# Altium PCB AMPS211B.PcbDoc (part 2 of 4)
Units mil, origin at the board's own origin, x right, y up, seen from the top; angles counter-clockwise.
Board outline 3600 x 2600 mil, 4 copper layers (Top Layer, GND, Power, Bottom Layer), stack 61.6 mil thick; 202 components, 101 nets, 561 pads, 317 vias.
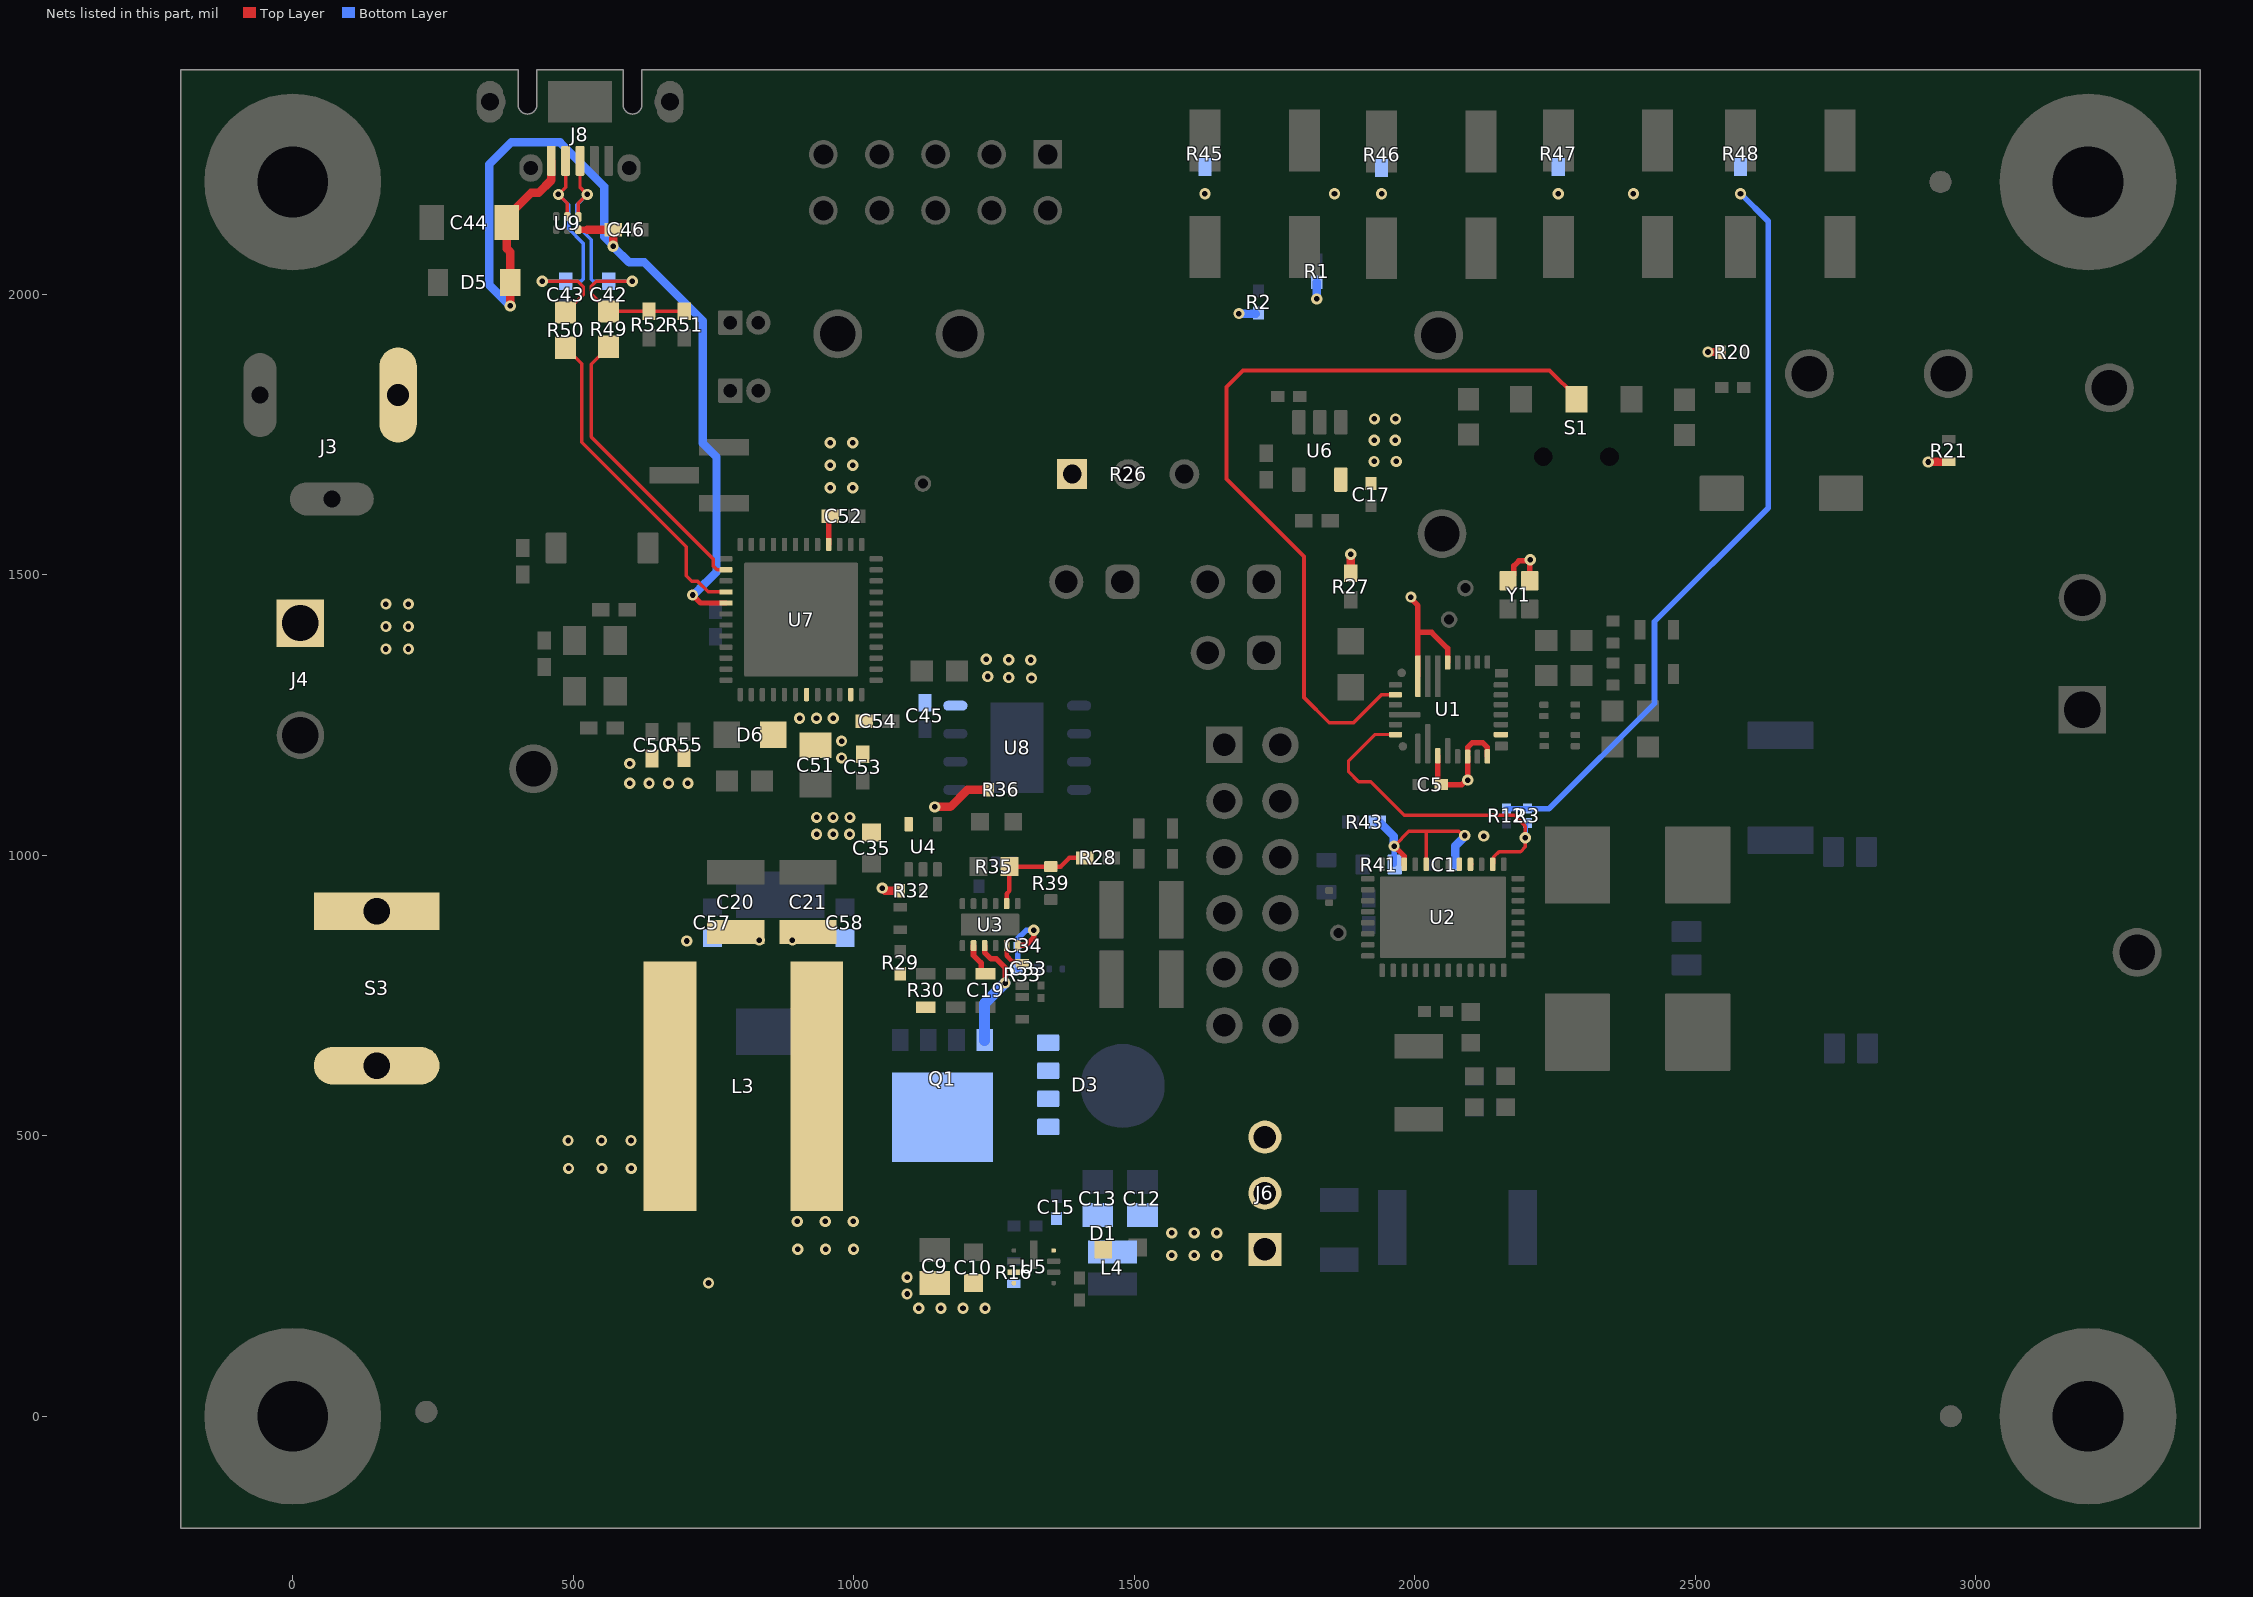
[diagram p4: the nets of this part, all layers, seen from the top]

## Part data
C1 C5 C16: library part CMP-0006347-2, "CAP, CERM, 1 uF, 16 V, +/- 10%, X5R, 0402", Cap_Case=0402, Manufacturer="Taiyo Yuden", Supplier Part Number 1=587-3709-2-ND, TempCo=X5R, Tolerance_%=10%, Value1=Unknown, Value2=16V, ValueDisplayed=1uF
C2: library part CMP-0007508-5, "CAP, CERM, 1 uF, 50 V, +/- 10%, X7R, 0603", Cap_Case=0603, Manufacturer="Taiyo Yuden", Supplier Part Number 1=587-3247-1-ND, TempCo=X7R, Tolerance_%=10%, Value1=Unknown, Value2=50V, ValueDisplayed=1uF
C3: library part CMP-0085951-1, "CAP, CERM, 10 µF, 75 V,+/- 20%, X7R, AEC-Q200 Grade 1, 1210", Cap_Case=1210, Manufacturer=TDK, TempCo=X7R, Tolerance_%=20%, Value2=75V, ValueDisplayed=10µF
C4 C27 C28 C37 C38 C39: library part CMP-0007470-5, "CAP, CERM, 0.1 uF, 100 V, +/- 10%, X7R, 0603", Cap_Case=0603, Manufacturer=MuRata, Supplier Part Number 1=490-6439-1-ND, TempCo=X7R, Tolerance_%=10%, Value1=Unknown, Value2=100V, ValueDisplayed=0.1uF
C6: library part CMP-0006298-2, "CAP, CERM, 0.047 uF, 50 V, +/- 10%, X7R, 0402", Cap_Case=0402, Manufacturer=TDK, Supplier Part Number 1=445-7336-1-ND, TempCo=X7R, Tolerance_%=10%, Value1="0.06407 ohm", Value2=50V, ValueDisplayed=0.047uF
C7: library part CMP-0006623-2, "CAP, CERM, 0.1 uF, 6.3 V, +/- 10%, X7R, 0402", Cap_Case=0402, Manufacturer=MuRata, Supplier Part Number 1=GRM155R70J104KA01D-ND, TempCo=X7R, Tolerance_%=10%, Value1=Unknown, Value2=6.3V, ValueDisplayed=0.1uF
C8: library part CMP-0008959-2, "CAP, CERM, 22 uF, 10 V, +/- 10%, X7R, 1206", Cap_Case=1206, Manufacturer=MuRata, Supplier Part Number 1=490-5309-1-ND, TempCo=X7R, Tolerance_%=10%, Value1=Unknown, Value2=10V, ValueDisplayed=22uF
C9: library part CMP-0007977-2, "CAP, CERM, 2.2 uF, 50 V, +/- 10%, X7R, AEC-Q200 Grade 1, 0805", Cap_Case=0805, Manufacturer=TDK, Supplier Part Number 1=445-174216-1-ND, TempCo=X7R, Tolerance_%=10%, Value1="0.003288 ohm", Value2=50V, ValueDisplayed=2.2uF
C10 C35 C57 C58: library part CMP-0007078-4, "CAP, CERM, 0.1 uF, 50 V, +/- 10%, X7R, AEC-Q200 Grade 1, 0603", Cap_Case=0603, Manufacturer=TDK, Supplier Part Number 1=445-5666-1-ND, TempCo=X7R, Tolerance_%=10%, Value1="0.0296 ohm", Value2=50V, ValueDisplayed=0.1uF
C11: library part CMP-0084548-1, "CAP, CERM, 0.1 µF, 50 V,+/- 10%, X7R, AEC-Q200 Grade 1, 0402", Cap_Case=0402, Manufacturer=TDK, TempCo=X7R, Tolerance_%=10%, Value2=50V, ValueDisplayed=0.1µF
C12 C13: library part CMP-0079153-1, "CAP, CERM, 10 µF, 10 V,+/- 10%, X7R, AEC-Q200 Grade 1, 0805", Cap_Case=0805, Manufacturer=MuRata, Supplier Part Number 1=490-12646-1-ND, TempCo=X7R, Tolerance_%=10%, Value2=10V, ValueDisplayed=10µF
C14: library part CMP-0121787-1, "Multilayer Ceramic Capacitors 47nF ±10% 450V X7T SMD 0805", Manufacturer=TDK, Operating Temperature Range="-55°C to +125°C", TempCo=+22/-33%, Temperature Characteristic=X7T, Tolerance_%=0.1%, ValueDisplayed=47nF
C15 C17 C18: library part CMP-0080702-1, "CAP, CERM, 0.1 µF, 16 V,+/- 5%, X7R, AEC-Q200 Grade 1, 0402", Cap_Case=0402, Manufacturer=MuRata, Supplier Part Number 1=490-16433-1-ND, TempCo=X7R, Tolerance_%=5%, Value2=16V, ValueDisplayed=0.1µF
C19 C22: library part CMP-0007139-4, "CAP, CERM, 1 uF, 25 V, +/- 10%, X7R, AEC-Q200 Grade 1, 0603", Cap_Case=0603, Manufacturer=MuRata, Supplier Part Number 1=490-10673-1-ND, TempCo=X7R, Tolerance_%=10%, Value1=Unknown, Value2=25V, ValueDisplayed=1uF
C20 C21: library part CMP-0080066-1, "CAP, CERM, 22 µF, 25 V,+/- 10%, X7R, 1210", Cap_Case=1210, Manufacturer="Samsung Electro-Mechanics", Supplier Part Number 1=1276-3391-1-ND, TempCo=X7R, Tolerance_%=10%, Value2=25V, ValueDisplayed=22µF
C23 C24 C25 C26: library part CMP-0079201-1, "CAP, CERM, 10 µF, 50 V,+/- 10%, X7R, 1210", Cap_Case=1210, Manufacturer="Samsung Electro-Mechanics", Supplier Part Number 1=1276-3388-1-ND, TempCo=X7R, Tolerance_%=10%, Value1="0.005 ohm", Value2=50V, ValueDisplayed=10µF
C29 C30: library part CMP-0007082-4, "CAP, CERM, 0.01 uF, 100 V, +/- 10%, X7R, AEC-Q200 Grade 1, 0603", Cap_Case=0603, Manufacturer=TDK, Supplier Part Number 1=445-5812-1-ND, TempCo=X7R, Tolerance_%=10%, Value1="0.235428 ohm", Value2=100V, ValueDisplayed=0.01uF
C31: library part CMP-0088625-1, "0.15µF ±20% 10V Ceramic Capacitor X7R 0402 (1005 Metric)", Digikey Part Number=445-12236-1-ND, Manufacturer=TDK, Mouser Part Number=810-CGA2B1X7R1A154MC, Operating Temperature Range="-55°C to +125°C", TempCo=15%, Temperature Characteristic=X7R, Tolerance_%=20%, ValueDisplayed=150nF
C32: library part CMP-0009645-3, "CAP, CERM, 1000 pF, 25 V, +/- 10%, X7R, AEC-Q200 Grade 1, 0201", Cap_Case=0201_033, Manufacturer=TDK, Supplier Part Number 1=445-12085-1-ND, TempCo=X7R, Tolerance_%=10%, Value1="2.5722 ohm", Value2=25V, ValueDisplayed=1000pF
C33: library part CMP-0088629-1, "Multilayer Ceramic Capacitor 0.047uF 10V 10% 0402 Paper T/R", Digikey Part Number=587-6577-1-ND, Manufacturer="Taiyo Yuden", Mouser Part Number=963-LMF105B7473KVHF, Operating Temperature Range="-55°C to +125°C", TempCo=15%, Temperature Characteristic=X7R, Tolerance_%=10%, ValueDisplayed=0.047uF
C34: library part CMP-0009735-1, "CAP, CERM, 1800 pF, 10 V, +/- 10%, X7R, 0201", Cap_Case=0201, Manufacturer=MuRata, Supplier Part Number 1=GRM033R71A182KA01D-ND, TempCo=X7R, Tolerance_%=10%, Value1=Unknown, Value2=10V, ValueDisplayed=1800pF
C36: library part CMP-0860561-1, "CAP, CERM, 0.01 µF, 25 V,+/- 10%, X7R, 0402", Cap_Case=0402, Manufacturer="Samsung Electro-Mechanics", TempCo=X7R, Tolerance_%=10%, Value2=25V, ValueDisplayed=0.01µF
C40 C41: library part CMP-0860379-1, "CAP, CERM, 18 pF, 50 V,+/- 5%, C0G/NP0, 0402", Cap_Case=0402, Manufacturer="Samsung Electro-Mechanics", TempCo=C0G/NP0, Tolerance_%=5%, Value2=50V, ValueDisplayed=18pF
C42 C43: library part CMP-0006307-2, "CAP, CERM, 10 pF, 50 V, +/- 5%, C0G/NP0, AEC-Q200 Grade 1, 0402", Cap_Case=0402, Manufacturer=TDK, Supplier Part Number 1=445-5584-1-ND, TempCo=C0G/NP0, Tolerance_%=5%, Value1=Unknown, Value2=50V, ValueDisplayed=10pF
C44: library part CMP-0082300-1, "CAP, CERM, 4.7 µF, 25 V,+/- 10%, X7R, AEC-Q200 Grade 1, 1206", Cap_Case=1206, Manufacturer=MuRata, Supplier Part Number 1=490-4794-1-ND, TempCo=X7R, Tolerance_%=10%, Value2=25V, ValueDisplayed=4.7µF
C45 C46 C52 C53 C54: library part CMP-0860188-1, "CAP, CERM, 0.1 µF, 16 V,+/- 10%, X7R, 0402", Cap_Case=0402, Manufacturer="Taiyo Yuden", TempCo=X7R, Tolerance_%=10%, Value2=16V, ValueDisplayed=0.1µF
C47 C49: library part CMP-0080612-1, "CAP, CERM, 0.22 µF, 10 V,+/- 10%, X7R, AEC-Q200 Grade 1, 0402", Cap_Case=0402, Manufacturer="Taiyo Yuden", Supplier Part Number 1=587-3770-1-ND, TempCo=X7R, Tolerance_%=10%, Value2=10V, ValueDisplayed=0.22µF
C48: library part CMP-0006946-4, "CAP, CERM, 0.47 uF, 10 V, +/- 10%, X7R, 0603", Cap_Case=0603, Manufacturer=Kemet, Supplier Part Number 1=399-4923-1-ND, TempCo=X7R, Tolerance_%=10%, Value1=Unknown, Value2=10V, ValueDisplayed=0.47uF
C50: library part CMP-0006254-2, "CAP, CERM, 1000 pF, 50 V, +/- 5%, C0G/NP0, 0402", Cap_Case=0402, Manufacturer=TDK, Supplier Part Number 1=445-13785-1-ND, TempCo=C0G/NP0, Tolerance_%=5%, Value1=Unknown, Value2=50V, ValueDisplayed=1000pF
C51: library part CMP-0078154-1, "CAP, CERM, 10 µF, 16 V,+/- 20%, X5R, 0805", Cap_Case=0805, Manufacturer="Wurth Elektronik", Supplier Part Number 1=732-7624-1-ND, TempCo=X5R, Tolerance_%=20%, Value2=16V, ValueDisplayed=10µF
C55 C56: library part CMP-0097864-2, "C0805 8.2 nF C0G 30ppm/°C 5.00% 250 V", Digikey Part Number=399-11901-2-ND, Manufacturer=KEMET, Mouser Part Number=80-C0805C822JAGAUTO, Operating Temperature Range="-55°C to +125°C", Part Number=C0805C822JAGACAUTO, TempCo=30ppm/°C, Temperature Characteristic=C0G, Tolerance_%=0.05%, ValueDisplayed=8.2nF
D1: library part CMP-0079921-3, "LED, Green, SMD", Color=Green, Manufacturer=Lite-On, PartNumber=LTST-C193KGKT-5A, Value1=W, Value2=2V
D2: library part CMP-0002829-3, "LED, Red, SMD", Color=red, Manufacturer=Lite-On, Value1=W, Value2=2V
D3: library part CMP-0088390-3, "Diode Schottky 45V 30A Surface Mount FlatPAK (5x6)", Digikey Part Number=V30K45-01HM3/HCT-ND, Forward Current=5A, Manufacturer=Vishay, Max Surge Forward Current=240A, Mouser Part Number=78-V30K45-01HM3/H, Operating Temperature Range="-40°C to +150°C", Peak Reverse Current=2mA, ValueDisplayed=4000pF
D4: library part CMP-0002938-3, "LED, Blue, SMD", Color=Blue, Manufacturer=Lite-On, PartNumber=LTST-C193TBKT-5A, Power_TotalModule=76mW, Value1=0.076W, Value2=2.8V
D5: library part CMP-0005803-3, "Diode, Zener, 5.6 V, 500 mW, SOD-123", Manufacturer="Diodes Inc.", PartNumber=MMSZ5232B-7-F, Power_W=500mW, Value1=0.5W
D6: library part CMP-0002830-3, "LED, Green, SMD", Color=green, Manufacturer=Lite-On, PartNumber=LTST-C171GKT, Value1=W, Value2=2.1V
FID1 FID2 FID3 FID4 FID5 FID6: library part CMP-0077181-1, "Fiducial mark.  There is nothing to buy or mount.", Manufacturer=N/A
H1 H2 H3 H4: library part CMP-0003617-1, "Machine Screw, Round, #4-40 x 1/4, Nylon, Philips panhead", Manufacturer="B&F Fastener Supply", Supplier Part Number 1=H542-ND
H5 H6 H7 H8: library part CMP-0003610-1, "Standoff, Hex, 0.5\"L #4-40 Nylon", Manufacturer=Keystone, Supplier Part Number 1=36-1902C-ND
J1: library part CMP-0075051-2, "Header (shrouded), 100mil, 5x2, Gold, TH", Manufacturer="Omron Electronic Components", Supplier Part Number 1=OR896-ND
J2 J4: library part CMP-0055345-1, "Terminal Block, 5.08mm, 2x1, TH", Color=Black, Current_A=15A, Manufacturer=Molex, PartNumber=039544-3002, Supplier Part Number 1=WM7853-ND, Voltage_V=300V
J3: library part CMP-0074931-1, "Power Jack, mini, 2.5mm OD, R/A, TH", Manufacturer=Switchcraft, PartNumber=RAPC712X, Supplier Part Number 1=SC237-ND
J5: library part CMP-0054551-2, "Header, 100mil, 6x2, Tin, TH", Color=Black, Current_A=3A, Manufacturer="Sullins Connector Solutions", Supplier Part Number 1=S2012E-06-ND, Voltage_V=1.8kV
J6: library part CMP-0002338-1, "Header, 100mil, 3x1, Tin, TH", Color=Black, Current_A=3A, Manufacturer="Sullins Connector Solutions", Supplier Part Number 1=S1012E-03-ND, Voltage_V=1.8kV
J7 J9: library part CMP-0097269-1, "Connector Header Through Hole 2 position 0.050\" (1.27mm)", Current_A=1A, Digikey Part Number=952-3598-ND, Manufacturer=Harwin, Mouser Part Number=855-M50-3530242, Operating Temperature Range="-40°C to +105°C"
J8: library part CMP-0094459-2, "USB - micro AB - Receptacle Connector 5 Position Surface Mount, Right Angle; Through Hole", Digikey Part Number=WM14336CT-ND, Manufacturer=Molex, Mouser Part Number=538-47590-1001, Operating Temperature Range="-30°C to +85°C", Voltage_V=30V
J10: library part CMP-0054602-1, "Header, 1.27mm, 3x1, Gold, SMT", Current_A=1A, Manufacturer="Sullins Connector Solutions", Supplier Part Number 1=S9011E-03-ND, Voltage_V=500V
J11: library part CMP-0075508-2, "Header, 2.54 mm, 2x1, Tin, TH", Color=Black, Current_A=6.3A, Manufacturer=Samtec, PartNumber=TSW-102-07-T-S, Supplier Part Number 1=SAM1035-02-ND, Voltage_V=550V
J12 J13: library part CMP-0075508-2, "Header, 2.54 mm, 2x1, Tin, TH", Color=Black, Current_A=6.3A, Manufacturer=Samtec, Supplier Part Number 1=SAM1035-02-ND, Voltage_V=550V
L1 L2: library part CMP-0081476-2, "Inductor, Shielded, Metal Composite, 22 µH, 2.4 A, 0.1248 ohm, SMD", Digikey Part Number=SRP7050TA-220MCT-ND, Manufacturer=Bourns, Mouser Part Number=652-SRP7050TA-220M, Operating Temperature Range="-55°C to +150°C", Part Number=SRP7050TA-220M, Self Resonant Frequency=9MHz, Test Frequency=100kHz, Tolerance_%=20%
L3: library part CMP-0060953-1, "Inductor, Shielded, Composite, 6.8 uH, 18.5 A, 0.01 ohm, SMD", Manufacturer=Coilcraft, Supplier Part Number 1=994-XAL1010-682MEB, Value1="0.01 ohm", Value2=18.5A, ValueDisplayed=6.8uH
L4: library part CMP-0061167-1, "Inductor, Shielded, Composite, 10 uH, 0.61 A, 0.56 ohm, SMD", Manufacturer=Coilcraft, Value1="0.56 ohm", Value2=0.61A, ValueDisplayed=10uH
LBL1: library part CMP-0003625-1, "Thermal Transfer Printable Labels, 0.650\" W x 0.200\" H - 10,000 per roll", Manufacturer=Brady, Supplier Part Number 1=97C5133
LOGO5: library part CMP-0074835-1, "IEC 61010-1 High Voltage Warning"
Q1: library part CMP-0000853-1, "MOSFET, N-CH, 60 V, 71 A, SO-8FL", Alternate Manufacturer=None, Manufacturer="ON Semiconductor", Supplier Part Number 1=NTMFS5C670NLT1GOSCT-ND, Value1=0.008, Value2="20 nC"
R1 R2: library part CMP-0026890-5, "RES, 2.2 k, 5%, 0.063 W, AEC-Q200 Grade 0, 0402", Manufacturer=Vishay-Dale, Power_W=63mW, Supplier Part Number 1=541-2.2KJCT-ND, TempCo="200 ppm/C", Tolerance_%=5%, Value2=0.063W, Value_Code=2k20, ValueDisplayed=2.2k
R3 R12: library part CMP-0027789-1, "RES, 5.10 k, 1%, 0.05 W, 0201", Manufacturer="Yageo America", Power_W=50mW, Supplier Part Number 1=YAG2741CT-ND, TempCo="200 ppm/C", Tolerance_%=1%, Value2=0.05W, Value_Code=5k10, ValueDisplayed=5.10k
R4: library part CMP-0098465-1, "1 Ohms ±1% 3W Chip Resistor 2010 (5025 Metric) Automotive AEC-Q200, Current Sense, Moisture Resistant, Pulse Withstanding", Digikey Part Number=4423-VMP-1R00-1.0-UCT-ND, Manufacturer=Isabellenhuette, Operating Temperature Range="-65°C to +170°C", Power_W=3W, TempCo=20ppm/°C, Tolerance_%=1%
R5: library part CMP-0015919-3, "RES, 22, 5%, 1.5 W, AEC-Q200 Grade 0, 2512", Manufacturer=Vishay-Dale, Power_W=1.5W, TempCo="200 ppm/C", Tolerance_%=5%, Value_Code=22R0, ValueDisplayed=22
R6 R7: library part CMP-0025885-5, "RES, 0, 5%, 0.1 W, 0603", Manufacturer=Yageo, Power_W=100mW, Supplier Part Number 1=311-0.0GRCT-ND, TempCo="200 ppm/C", Tolerance_%=5%, Value2=0.1W, Value_Code=0000, ValueDisplayed=0
R8 R13: library part CMP-0098454-1, "6.04 kOhms ±0.1% 0.05W, 1/20W Chip Resistor 0201 (0603 Metric) Anti-Sulfur, Automotive AEC-Q200, Moisture Resistant Thin Film", Digikey Part Number=541-TNPW02016K04BEEDCT-ND, Manufacturer=Vishay, Operating Temperature Range="-55°C to +155°C", Power_W=75mW, TempCo=25ppm/°C, Tolerance_%=0.1%
R9 R14: library part CMP-0024226-3, "RES, 422 k, 0.1%, 0.1 W, 0603", Manufacturer="Yageo America", Power_W=100mW, TempCo="25 ppm/C", Tolerance_%=0.1%, Value2=0.1W, Value_Code=422k
R10 R15: library part CMP-0098464-1, "2 kOhms ±0.1% 0.05W, 1/20W Chip Resistor 0201 (0603 Metric) Anti-Sulfur, Automotive AEC-Q200, Moisture Resistant Thin Film", Digikey Part Number=541-TNPW02012K00BEEDCT-ND, Manufacturer="Vishay Dale", Mouser Part Number=71-TNPW02012K00BEED, Operating Temperature Range="-55°C to +155°C", Power_W=75mW, TempCo=25ppm/°C, Tolerance_%=0.1%
R11 R54: library part CMP-0082532-1, "RES, 499, 1%, 0.1 W, 0603", Manufacturer=Vishay-Dale, Power_W=100mW, Supplier Part Number 1=541-3986-1-ND, TempCo="100 ppm/C", Tolerance_%=1%, Value2=0.1W, Value_Code=499R, ValueDisplayed=499
R16 R20 R21 R32: library part CMP-0078669-1, "RES, 10.0 k, 1%, 0.063 W, 0402", Manufacturer="Yageo America", Power_W=63mW, Supplier Part Number 1=311-10.0KLRCT-ND, TempCo="100 ppm/C", Tolerance_%=1%, Value2=0.063W, Value_Code=10k0, ValueDisplayed=10.0k
R17 R23: library part CMP-0024046-3, "RES, 294 k, 0.1%, 0.1 W, 0603", Manufacturer="Yageo America", Power_W=100mW, TempCo="25 ppm/C", Tolerance_%=0.1%, Value2=0.1W, Value_Code=294k
R18 R24: library part CMP-0095259-2, "1.3 MOhms ±0.1% 0.125W, 1/8W Chip Resistor 0603 (1608 Metric) Anti-Sulfur, Automotive AEC-Q200 Thin Film", Digikey Part Number=541-MCT0603MD1304BP500CT-ND, Manufacturer="Vishay Dale", Mouser Part Number=594-MCT0603MD1304BP5, Operating Temperature Range="-55°C to +155°C", Power_W=125mW, TempCo=25ppm/°C, Tolerance_%=0.1%
R19 R25: library part CMP-0097226-1, "Res Thin Film 0402 6.34K Ohm 0.1% 1/16W ±25ppm/°C Molded SMD Paper T/R", Digikey Part Number=YAG4303CT-ND, Manufacturer=Yageo, Mouser Part Number=603-RT0402BRD076K34L, Operating Temperature Range="-55°C to +155°C", Power_W=63mW, TempCo=25ppm/°C, Tolerance_%=0.1%
R22: library part CMP-0026992-3, "RES, 0, 5%, 0.1 W, AEC-Q200 Grade 0, 0402", Manufacturer=Panasonic, Power_W=100mW, Supplier Part Number 1=P0.0JCT-ND, TempCo="600 ppm/C", Tolerance_%=5%, Value2=0.1W, Value_Code=0000, ValueDisplayed=0
R26: library part CMP-0093882-3, "10 kOhms 0.5W, 1/2W Through Hole Thumbwheel Potentiometer Top Adjustment", Digikey Part Number=3352T-103LF-ND, Manufacturer=Bourns, Mouser Part Number=652-3352T-1-103LF, Operating Temperature Range="-55°C to +125°C", Power=500mW, Power_W=0.5W, TempCo=100ppm/°C, Tolerance_%=20%, Voltage=250V
R27: library part CMP-0026402-2, "RES, 499, 1%, 0.063 W, AEC-Q200 Grade 0, 0402", Manufacturer=Vishay-Dale, Power_W=63mW, Supplier Part Number 1=541-499LCT-ND, TempCo="100 ppm/C", Tolerance_%=1%, Value2=0.063W, Value_Code=499R, ValueDisplayed=499
R28: library part CMP-0026622-3, "RES, 9.76 k, 1%, 0.063 W, AEC-Q200 Grade 0, 0402", Manufacturer=Vishay-Dale, Power_W=63mW, Supplier Part Number 1=541-9.76KLCT-ND, TempCo="100 ppm/C", Tolerance_%=1%, Value2=0.063W, Value_Code=9k76, ValueDisplayed=9.76k
R29: library part CMP-0026659-2, "RES, 100 k, 1%, 0.1 W, 0402", Manufacturer=Panasonic, Power_W=100mW, TempCo="100 ppm/C", Tolerance_%=1%, Value2=0.1W, Value_Code=100k
R30: library part CMP-0022003-4, "RES, 10.0, 1%, 0.1 W, AEC-Q200 Grade 0, 0603", Manufacturer=Vishay-Dale, Power_W=100mW, Supplier Part Number 1=541-10.0HCT-ND, TempCo="100 ppm/C", Tolerance_%=1%, Value2=0.1W, Value_Code=10R0, ValueDisplayed=10.0
R31: library part CMP-0026163-2, "RES, 20.5 k, 1%, 0.063 W, AEC-Q200 Grade 0, 0402", Manufacturer=Vishay-Dale, Power_W=63mW, Supplier Part Number 1=541-20.5KLCT-ND, TempCo="100 ppm/C", Tolerance_%=1%, Value2=0.063W, Value_Code=20k5, ValueDisplayed=20.5k
R33: library part CMP-0026501-2, "RES, 665, 1%, 0.063 W, AEC-Q200 Grade 0, 0402", Manufacturer=Vishay-Dale, PartNumber=CRCW0402665RFKED, Power_W=63mW, Supplier Part Number 1=541-665LCT-ND, TempCo="100 ppm/C", Tolerance_%=1%, Value2=0.063W, Value_Code=665R, ValueDisplayed=665
R34: library part CMP-0026656-1, "RES, 100, 1%, 0.1 W, 0402", Manufacturer=Panasonic, Power_W=100mW, Supplier Part Number 1=P100LCT-ND, TempCo="100 ppm/C", Tolerance_%=1%, Value2=0.1W, Value_Code=100R, ValueDisplayed=100
R35: library part CMP-0021990-4, "RES, 100 k, 1%, 0.1 W, AEC-Q200 Grade 0, 0603", Manufacturer=Vishay-Dale, Power_W=100mW, Supplier Part Number 1=541-100KHCT-ND, TempCo="100 ppm/C", Tolerance_%=1%, Value2=0.1W, Value_Code=100k
R36: library part CMP-0026022-3, "RES, 150, 1%, 0.063 W, AEC-Q200 Grade 0, 0402", Manufacturer=Vishay-Dale, Power_W=63mW, Supplier Part Number 1=541-150LCT-ND, TempCo="100 ppm/C", Tolerance_%=1%, Value2=0.063W, Value_Code=150R, ValueDisplayed=150
R37: library part CMP-0026399-2, "RES, 48.7 k, 1%, 0.063 W, AEC-Q200 Grade 0, 0402", Manufacturer=Vishay-Dale, Power_W=63mW, Supplier Part Number 1=541-48.7KLCT-ND, TempCo="100 ppm/C", Tolerance_%=1%, Value2=0.063W, Value_Code=48k7, ValueDisplayed=48.7k
R38: library part CMP-0015751-2, "RES, 0.005, 1%, 3 W, AEC-Q200 Grade 0, 2512", Manufacturer=Bourns, Power_W=3W, Supplier Part Number 1=CRE2512-FZ-R005E-3CT-ND, TempCo="75 ppm/C", Tolerance_%=1%, Value_Code=5L000, ValueDisplayed=0.005
R39: library part CMP-0098378-1, "3.48 kOhms ±1% 0.1W, 1/10W Chip Resistor 0603 (1608 Metric) Automotive AEC-Q200, Moisture Resistant Thick Film", Approved Alternate Part Number=541-1.00HHCT-ND, Digikey Part Number=2019-RK73H1JTTD3481FCT-ND, Manufacturer="KOA Speer", Mouser Part Number=660-RK73H1JTTD3481F, Operating Temperature Range="-55°C to +155°C", Power=100mW, TempCo=100ppm/°C, Tolerance_%=1%, Voltage=75V
R40: library part CMP-0088609-1, "Res Thick Film 0201 2.26K Ohm 1% 1/20W ±200ppm/°C Molded SMD SMD T/R", Digikey Part Number=P122840CT-ND, Manufacturer="Panasonic Electronic Components", Mouser Part Number=667-ERJ-1GNF2261C, Operating Temperature Range="-55°C to +125°C", Power_W=50mW, TempCo=200%, Tolerance_%=1%
R41 R42: library part CMP-0097467-1, "0 Ohms Jumper 0.125W, 1/8W Chip Resistor 0603 (1608 Metric) Automotive AEC-Q200 Thick Film", Digikey Part Number=10-ERJ-H3G0R00VCT-ND, Manufacturer=Panasonic, Mouser Part Number=667-ERJ-H3G0R00V, Operating Temperature Range="-55°C to +175°C", Part Number=ERJ-H3G0R00V, Power_W=125mW
R43 R55: library part CMP-0026935-3, "RES, 47 k, 5%, 0.063 W, AEC-Q200 Grade 0, 0402", Manufacturer=Vishay-Dale, Power_W=63mW, Supplier Part Number 1=541-47KJCT-ND, TempCo="200 ppm/C", Tolerance_%=5%, Value2=0.063W, Value_Code=47k0, ValueDisplayed=47k
R44: library part CMP-0026477-2, "RES, 5.11, 1%, 0.063 W, AEC-Q200 Grade 0, 0402", Manufacturer=Vishay-Dale, Power_W=63mW, Supplier Part Number 1=541-5.11LLCT-ND, TempCo="100 ppm/C", Tolerance_%=1%, Value2=0.063W, Value_Code=5R11, ValueDisplayed=5.11
R45 R46 R47 R48: library part CMP-0026825-5, "RES, 10 k, 5%, 0.063 W, AEC-Q200 Grade 0, 0402", Manufacturer=Vishay-Dale, Power_W=63mW, Supplier Part Number 1=541-10KJCT-ND, TempCo="200 ppm/C", Tolerance_%=5%, Value2=0.063W, Value_Code=10k0, ValueDisplayed=10k
R49 R50: library part CMP-0022967-4, "RES, 27.4, 1%, 0.1 W, 0603", Manufacturer=Yageo, Power_W=100mW, Supplier Part Number 1=311-27.4HRCT-ND, TempCo="100 ppm/C", Tolerance_%=1%, Value2=0.1W, Value_Code=27R4, ValueDisplayed=27.4
R51: library part CMP-0026085-3, "RES, 1.40 k, 1%, 0.063 W, AEC-Q200 Grade 0, 0402", Manufacturer=Vishay-Dale, Power_W=63mW, Supplier Part Number 1=541-1.40KLCT-ND, TempCo="100 ppm/C", Tolerance_%=1%, Value2=0.063W, Value_Code=1k40, ValueDisplayed=1.40k
R52: library part CMP-0026859-2, "RES, 1.0 M, 5%, 0.063 W, AEC-Q200 Grade 0, 0402", Manufacturer=Vishay-Dale, Power_W=63mW, Supplier Part Number 1=541-1.0MJCT-ND, TempCo="200 ppm/C", Tolerance_%=5%, Value2=0.063W, Value_Code=1M00, ValueDisplayed=1.0M
R53: library part CMP-0025951-3, "RES, 100, 1%, 0.063 W, AEC-Q200 Grade 0, 0402", Manufacturer=Vishay-Dale, Power_W=63mW, Supplier Part Number 1=541-100LCT-ND, TempCo="100 ppm/C", Tolerance_%=1%, Value2=0.063W, Value_Code=100R, ValueDisplayed=100
R57: library part CMP-0091760-1, "0 Ohms Jumper 0.1W, 1/10W, 5.8A Chip Resistor 0201 (0603 Metric) Automotive AEC-Q200 Metal Foil", Manufacturer="Stackpole Electronics", Operating Temperature Range="-55°C to +155°C", Part Number=HCJ0201ZT0R00, Power_W=100mW
S1: library part CMP-0002305-1, "Switch, SPDT, Slide, On-On, 2 Pos, 0.1 A, 12 VDC, R/A, SMD", CurrentRating_mA=100A, Manufacturer="C&K Components", PartNumber=AYZ0102AGRLC, Supplier Part Number 1=401-2012-1-ND
S2: library part CMP-0002323-1, "Switch, SPST-NO, Off-Mom, 0.05 A, 12 VDC, SMD", CurrentRating_mA=50A, Manufacturer=Panasonic, PartNumber=EVQ-5PN04K, Supplier Part Number 1=P13595SCT-ND
S3: library part CMP-0002275-1, "Switch, SPST, Off-On, 10A, 125 V, TH", CurrentRating_mA=10kA, Manufacturer=Conergy, Supplier Part Number 1=CH755-ND
S4 S5 S6 S7: library part CMP-0002241-1, "Switch, SPST-NO, Off-Mom, 0.05 A, 12 V, SMT", CurrentRating_mA=50A, Manufacturer=E-Switch, PartNumber=TL3301AF160QJ, Supplier Part Number 1=EG4374CT-ND
S8: library part CMP-0002143-3, "Switch, Tactile, SPST-NO, 0.05A, 12V, SMT", CurrentRating_mA=50A, Manufacturer=E-Switch, PartNumber=TL1015AF160QG, Supplier Part Number 1=EG4344CT-ND
SH1 SH2: library part CMP-0097239-3, "1.27 mm, 2 Pos. Female Jumper Socket, Handle Shunt, Black", Current_A=1A, Digikey Part Number=952-1731-ND, Manufacturer=Harwin, Mouser Part Number=855-M50-2000005, Operating Temperature Range="-40°C to +105°C"
SH-J1 SH-J2 SH-J3 SH-J4 SH-J5 SH-J6 SH-J7 SH-J8 SH-J9: library part CMP-0003677-2, "Shunt, 100mil, Gold plated, Black", Manufacturer="TE Connectivity", Supplier Part Number 1=A26242-ND
TP1 TP2 TP3: library part CMP-0055158-2, "Test Point, Multipurpose, Green, TH", Color=Green, Manufacturer="Keystone Electronics", Supplier Part Number 1=36-5126-ND
TP4 TP5: library part CMP-0055150-2, "Test Point, Multipurpose, Orange, TH", Color=Orange, Manufacturer="Keystone Electronics", Supplier Part Number 1=36-5013-ND
TP6 TP7 TP8 TP14: library part CMP-0003719-1, "Testpoint", Manufacturer="Texas Instruments"
TP9 TP10: library part CMP-0055148-2, "Test Point, Multipurpose, Black, TH", Color=Black, Manufacturer="Keystone Electronics", Supplier Part Number 1=36-5011-ND
TP12 TP13: library part CMP-0055147-2, "Test Point, Multipurpose, Red, TH", Color=Red, Manufacturer="Keystone Electronics", Supplier Part Number 1=36-5010-ND
U1: library part CMP-0096127-4, "Configurable Ultrasonic PWM Driver With I/V Sense Amplifiers", Manufacturer="Texas Instruments", Operating Temperature Range="-65°C to +150°C"
U2: library part CMP-0049717-3, "Full-Bridge PWM Input Piezo Driver for Ultrasonic Lens Cleaning", Manufacturer="Texas Instruments", Max Supply Voltage=35V, Min Supply Voltage=4.5V, Nominal Supply Current=5-19mA, Operating Temperature Range="-40°C to +150°C"
U3: library part CMP-0081539-1, "Automotive Grade 2.2-MHz Wide Input Non-synchronous Boost Controller, DSS0012C (WSON-12)", Alternate Manufacturer="Texas Instruments", Alternate PartNumber=LM5155QDSSTQ1
U4: library part CMP-0051661-3, "Automotive Catalog Single Inverter, DCK0005A, LARGE T&R", F @ Nom Voltage(Max)(Mhz)=150, Generic Part Number=SN74LVC1G04-Q1, ICC @ Nom Voltage(Max)(mA)=0.01, Manufacturer="Texas Instruments", Operating Temperature Range(C)="-40 to 125", Rating=Automotive, tpd @ Nom Voltage(Max)(ns)=7.5,5.2,4.2,3.7, Voltage(Nom)(V)=1.8,2.5,3.3,5
U5: library part CMP-0750083-1, "LMR36503/06-Q1 Wide Input 60-V Synchronous, DC-DC Buck Converter, RPE0009A (VQFN-9)", Alternate Manufacturer="Texas Instruments", Alternate PartNumber=LMR36503MSC3RPERQ1
U6: library part CMP-0032028-2, "CMOS Amplifier 1 Circuit Rail-to-Rail SOT-23-5", Digikey Part Number=296-TLV365DBVRCT-ND, Input Bias Current=0.000005uA, Input Offset Voltage=0.4mV, Manufacturer="Texas Instruments", Max Supply Voltage=5.5V, Min Supply Voltage=2.2V, Mouser Part Number=595-TLV365DBVR, Nominal Supply Current=4.6mA, Operating Temperature Range="-40°C to +125°C", Output Current Per Channel=85mA, Voltage Gain=120dB
U7: library part CMP-0038981-3, "Mixed Signal Microcontroller, RGZ0048A (VQFN-48)", Frequency(MHz)=25, Manufacturer="Texas Instruments", Operating Temperature Range="-40 to 85 C", Rating=Catalog, Temp Sensor=Yes
U8: library part CMP-0005244-2, "512K I2C Serial EEPROM, DFN-8", Manufacturer=Microchip, Supplier Part Number 1=24FC512-I/MF-ND
U9: library part CMP-0043115-3, "4-Channel ESD Protection Array for High-Speed Data Interfaces, DRY0006A (USON-6)", Breakdown Voltage(Min)(V)=6, IO Capacitance(Typ)(pF)=1.6, IO Leakage Current(nA)=1, Manufacturer="Texas Instruments", Operating Temperature Range="-40 to 85 C", Rating=Catalog
Y1: library part CMP-0088558-2, "10MHz XO (Standard) CMOS Oscillator 3.3V Enable/Disable 4-SMD, No Lead", Digikey Part Number=1923-1639-1-ND, Frequency Stability=5ppm, Frequency_Fixed=10MHz, Load Capacitance=15pF, Manufacturer=IQD, Max Supply Current=6mA, Max Supply Voltage=3.63V, Min Supply Voltage=2.97V, Mouser Part Number=449-LFSPXO071190REEL, Operating Temperature Range="-40°C to +125°C"
Y2: library part CMP-0004583-3, "Crystal, 24.000 MHz, 18pF, SMD", Frequency Stability=+/-50ppm, Frequency_Fixed=24MHz, Manufacturer="Abracon Corporation", Supplier Part Number 1=535-9138-1-ND
ZZ1: library part CMP-0003616-3
ZZ2: library part CMP-0077236-1
ZZ3: library part CMP-0077237-1
ZZ4 ZZ5: library part CMP-0077238-1

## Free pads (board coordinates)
  rrect100% 41.34x49.21 on Top Paste mask+0: ""(424.41,2224.8) ""(599.61,2224.8)

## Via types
v1: diameter 20, hole 10, Top Layer to Bottom Layer, tented both sides, 277 vias
v2: diameter 19.68, hole 7.87, Top Layer to Bottom Layer, 24 vias
v3: diameter 19.68, hole 7.87, Top Layer to Bottom Layer, tented both sides, 16 vias

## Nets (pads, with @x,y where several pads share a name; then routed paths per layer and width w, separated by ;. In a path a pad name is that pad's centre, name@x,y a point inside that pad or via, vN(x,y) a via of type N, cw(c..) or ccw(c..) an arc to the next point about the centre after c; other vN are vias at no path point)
3.3V-DRV: C1.1 J6.3 R41.2 R43.2 U2.24 U2.25 U2.28 U2.30 | length 387.6
  Top Layer w6: v1@1963,1017 1963.84,1017 1989.37,1042.53 2020.52,1042.53 2078.49,1042.53 2086.01,1035 v1(2089,1035) ; U2.28@2020.52,983.76 2020.52,1041.48
  Top Layer w9.5: v1(1963.1,1016.25) 1981.14,998.21 U2.30@1981.14,983.88 ; U2.24@2099.26,983.76 U2.24@2099.43,983.93
  Bottom Layer w9.5: R41.2@1963.19,983.27 v1@1963.19,1016
  Bottom Layer w10: v1(2089,1035) v1@2090.17,1036.17
  Bottom Layer w15: R43.2@1933.07,1059.06 1937.01,1059.06 1962.14,1033.92 v1@1962.14,1016.86 ; C1.1@2072.19,982.75 2072.19,1016.84 2089,1033.65 v1(2089,1035)
  other v1: 2123,1034
3.3V-MSP: C12.1 C13.1 C15.1 C17.1 C35.1 C45.1 C50.1 C51.1 C52.1 C53.1 C54.1 D1.1 D6.1 J6.1 L4.2 R3.2 R12.2 R16.2 R26.1 R32.1 R36.1 R45.2 R46.2 R47.2 R48.2 R55.2 U4.5 U5.8 U6.5 U7.7 U7.11 U7.28 U8.8 | length 1551.5
  Top Layer w9.4: U7.28@955.2,1553.9 955.2,1601.37 C52.1@958.12,1604.29
  Top Layer w15: v1(1050.72,941.27) 1055.72,936.27 R32.1@1083.43,936.27 ; v1(1144.16,1086.09) 1172.16,1086.09 1202.61,1116.55 R36.1@1242.15,1116.55
  Bottom Layer w10: R12.2@2163.39,1082.68 2200.79,1082.68 2239.17,1082.68 2427.17,1270.67 2427.17,1416.34 2629.92,1619.09 2629.92,2129.92 v1@2580.71,2179.13
  other v1: 1566.88,286.68 1606.88,286.68 1646.88,286.68 1566.88,326.68 1606.88,326.68 1646.88,326.68 933.65,1037.39 963.13,1037.39 992.6,1037.39 933.65,1067.39 963.13,1067.39 993.13,1067.39 600.51,1128.08 635.1,1128.08 669.68,1128.08 704.26,1128.08 600.51,1163.24 978.21,1173.36 978.21,1203.37 903.47,1243.92 933.47,1243.92 963.47,1243.92 1316.82,1315.71 1276.16,1316.73 1238.63,1318.58 1276.16,1348.28 1315.53,1347.84 1236.2,1349.26 958.12,1655.11 998.12,1655.11 958.12,1695.1 998.12,1695.11 1927.4,1701.9 1966.72,1701.9 958.12,1735.11 998.12,1735.11 1927.69,1739.79 1965.31,1739.79 1927.98,1777.67 1965.6,1777.67 1625.85,2179.11 1856.8,2179.11 1940.82,2179.11 2255.78,2179.11 2389.63,2179.11 2580.58,2179.11
3.3V-ULC: C5.1 J6.2 R1.2 R2.2 R20.1 R21.1 R27.1 U1.13 U1.16 U1.27 U1.30 U1.32 Y1.1 Y1.4 | length 695.3
  Top Layer w9.8: v1(1993,1460) 1993,1457.24 2005.36,1444.88 2005.36,1397.09 ; U1.16@2005.36,1318.91 2005.36,1397.09 ; U1.27@2040.8,1177.18 2040.82,1128.47 C5.1@2043.31,1125.98 ; C5.1@2051.18,1129.92 2051.18,1128.96 2054.16,1125.98 2083.85,1125.98 2091.73,1133.86 v1(2094.49,1133.86) 2093.97,1134.38 U1.30@2093.97,1175.68 ; U1.13@2058.51,1343.52 2058.53,1368.63 2030.07,1397.09 2005.36,1397.09 ; U1.30@2093.97,1186 2093.97,1192.15 2102.6,1200.78 2120.72,1200.78 2129.36,1192.15 U1.32@2129.38,1176.2 ; Y1.1@2166.31,1489.21 2176.76,1499.66 2176.76,1515.76 2185.62,1524.62 2204.62,1524.62 v1@2205.3,1525.3 ; Y1.4@2204.72,1492.13 2205.3,1492.7 v1@2205.3,1525.3 ; v1@2205.57,1526.43 v1(2205.71,1526.57) ; v1@2206,1526 v1@2205.3,1525.3
  Top Layer w15: R27.1@1885.73,1502.47 v1(1885.73,1536.22) ; v1(2522.65,1896.85) R20.1@2546.4,1896.85 ; v1(2915.35,1700.79) 2915.67,1701.11 R21.1@2951.35,1701.11
  Bottom Layer w15: v1(1686.39,1965.39) R2.2@1716.2,1965.39 ; v1(1825.17,1991.5) R1.2@1825.17,2021.32
5V-USB: C44.1 C46.1 D5.1 J8.1 U7.41 U9.6 | length 1826
  Top Layer w9.4: v1(712.69,1463.76) 726.88,1449.57 U7.41@772.13,1449.57
  Top Layer w11.8: U9.6@509.05,2114.91 525.08,2114.91
  Top Layer w15: v1(387.7,1979.11) D5.1@387.7,2020.98 387.7,2075.08 381.7,2081.08 381.7,2137.54 424.7,2180.54 438.34,2180.54 460.83,2203.03 J8.1@460.83,2237.6 ; 525.08,2114.91 C46.1@571.04,2114.91 v1(571.04,2085.24)
  Bottom Layer w15: v1(387.7,1979.11) 350.08,2016.73 350.08,2231.44 389.14,2270.5 476.46,2270.5 555.07,2191.9 555.07,2102.56 571.04,2086.59 v1(571.04,2085.24) 599.71,2056.57 626.96,2056.57 731.15,1952.37 731.15,1733.95 755.25,1709.85 755.25,1504.66 736.47,1485.87 736.15,1485.87 714.04,1463.76 v1(712.69,1463.76)
12VIN: J3.1 J4.1 S3.1
  other v1: 166.09,1367.57 206.09,1367.57 166.09,1407.57 206.09,1407.57 166.09,1447.57 206.09,1447.57
12VIN_SW: C9.1 C10.1 C20.1 C21.1 C57.1 C58.1 L3.1 R29.2 R30.2 S3.2 U5.3 U5.4
  other v1: 1115.87,192.57 1155.27,192.57 1194.67,192.57 1234.07,192.57 1094.99,217.82 740.97,237.55 1094.99,247.82 491.75,441.77 551.09,441.77 603.32,441.77 490.84,491.55 550.4,491.55 602.86,491.55 702.28,847.06 831.58,848.7 890.63,848.7
AD0: S1.2 U1.19 | length 1472.5
  Top Layer w7: U1.19@1965.4,1285.92 1940.75,1285.92 1890.91,1236.07 1847.44,1236.07 1802.17,1281.35 1802.17,1532.25 1664.21,1670.2 1664.21,1834.49 1693.88,1864.17 2240.41,1864.17 2287.91,1816.67 S1.2@2287.91,1812.73
COMP: C33.2 C34.1 U3.6 | length 135.7
  Top Layer w10: U3.6@1292.23,839.68 1307.1,839.68 1320.89,853.47 v1(1320.89,866.06)
  Bottom Layer w10: C33.2@1292.15,797.23 C34.1@1292.15,838.83 1292.15,850.99 1307.22,866.06 v1(1320.89,866.06)
CS: R33.1 U3.5 | length 51.7
  Top Layer w8: U3.5@1272.46,838.83 1272.46,820.61 1282.87,810.21 1297.59,810.21 R33.1@1300.46,807.33
CVCC: C19.1 U3.2 | length 59.5
  Top Layer w9.84: U3.2@1213.41,838.83 1213.41,821.44 1227.02,807.83 1227.02,793.91 1228.79,793.91 C19.1@1233.87,788.83
D+: C42.1 J8.3 R49.2 R51.2 R52.2 U9.1 | length 625
  Top Layer w6.2: U9.1@509.05,2137.54 509.05,2161.9 v1(524.92,2177.77) 512.01,2190.68 J8.3@512.01,2237.6 ; v1(605,2022.95) 540.63,2022.95 531.99,2014.31 531.99,2000.49 R49.2@563.19,1969.29 R51.2@698.01,1969.29
  Bottom Layer w6.2: v1(524.92,2177.77) 506.59,2159.43 506.59,2122.59 532.18,2097 532.18,2026.58 535.81,2022.95 C42.1@563.19,2022.95 v1(605,2022.95)
D-: C43.1 J8.2 R50.2 U9.2 | length 490.4
  Top Layer w6.2: v1(444.61,2022.95) 508.04,2022.95 517.62,2013.38 517.62,1998.73 R50.2@486.42,1967.53 ; J8.2@486.42,2237.6 486.42,2190.68 v1(473.5,2177.77) 489.37,2161.9 U9.2@489.37,2138.53
  Bottom Layer w6.2: v1(444.61,2022.95) C43.1@486.42,2022.95 513.79,2022.95 517.42,2026.58 517.42,2090.89 491.83,2116.48 491.83,2159.44 v1(473.5,2177.77)
DM: R50.1 U7.40 | length 578.1
  Top Layer w6.2: R50.1@486.42,1904.53 514.93,1876.02 514.93,1736.28 701.5,1549.71 701.5,1498.07 711.52,1488.05 721.49,1488.05 740.29,1469.25 U7.40@772.13,1469.25
DP: R49.1 U7.38 | length 519.2
  Top Layer w6.2: R49.1@563.19,1906.3 531.99,1875.1 531.99,1745.46 749.16,1528.3 749.16,1515.94 756.24,1508.86 771.89,1508.86 U7.38@772.13,1508.62
DRAIN: D3.1 D3.2 D3.3 D3.4 L3.2 Q1.5
  other v1: 900.06,297.49 949.83,297.49 999.6,297.49 899.15,347.28 949.15,347.28 999.14,347.28
DREG: U1.2
FAULTZ: R3.1 U1.23 U2.22 | length 620.3
  Top Layer w6: U1.23@1965.4,1215.06 1928.64,1215.06 1881.89,1168.31 1881.89,1148.62 1899.61,1130.91 1921.26,1130.91 1981,1071.17 2177.83,1071.17 2197,1052 v1(2197,1031) 2197,1015 2188.44,1006.44 2150.04,1006.44 2140.55,996.95 2140.55,985.68 U2.22@2138.63,983.76
  Bottom Layer w6: v1(2197,1031) 2198.89,1032.89 2198.89,1055.19 R3.1@2200.79,1057.09
FB: R28.1 R35.1 R39.2 U3.8 | length 208.5
  Top Layer w8: U3.8@1272.46,913.63 1272.46,931.29 1277.46,936.29 R35.1@1277.46,979.81 R39.2@1351.2,979.81 1368.86,979.81 1384.06,995.01 R28.1@1411.44,995.01
GATE: Q1.4 U3.3 | length 204.3
  Top Layer w9.84: U3.3@1233.09,838.83 1233.09,826.8 1244.76,815.14 1254.15,815.14 1269.64,799.65 v1(1269.64,772.04)
  Bottom Layer w20: Q1.4@1233.09,670.26 1233.09,735.49 v1(1269.64,772.04)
